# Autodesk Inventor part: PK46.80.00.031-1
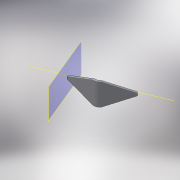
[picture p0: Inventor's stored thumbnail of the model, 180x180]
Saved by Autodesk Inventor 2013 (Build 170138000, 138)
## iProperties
Created: 2005-12
Part Number: PK46.80.00.031-1
Material: Steel, Mild
Document SubType Name: Листовой материал
Designer: SAlex
Manufacturer: Standard
Standards Organization: Custom
Density: 7.86 g/cm^3
Flat Pattern Width: 20.0383 cm
Flat Pattern Length: 20.0383 cm
Flat Pattern Area: 401.534 cm^2
Sheet Metal Rule: Default
Mass: 1079.17 g
Surface Area: 391.416 cm^2
Volume: 137.3 cm^3
Author: SAlex
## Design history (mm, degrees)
node "ФлнОтгиб1"
node "РабПлоскость1"
node "РабТочка1"
node "РабТочка2"
node "РабОсь1"
node "РабПлоскость2"
node "РабПлоскость3"
sketch "Эскиз4"
  geometry: L1 (141.716, 0)-(141.716, 150) reference; L2 (0, 150)-(141.716, 150) reference; L3 (0, 150)-(0, 0) reference; L4 (0, 0)-(141.716, 0) reference; L5 (141.716, 20.768)-(0, 75) reference; L6 (0, 75)-(141.716, 129.232) reference; 4 further points; 2 other entities
  constraints: 2 other
extrude "Выдавливание1" cut sketch "Эскиз4" stored distance "d11" = 10; taper "d12" = 0 deg
sketch "Эскиз5"
  geometry: L1 (141.716, 0)-(141.716, 150) reference; L2 (141.716, 150)-(0, 150) reference; L3 (0, 0)-(0, 150) reference; L4 (141.716, 0)-(0, 0) reference; L5 (0, 75)-(141.716, 129.232) reference; L6 (141.716, 20.768)-(0, 75) reference
extrude "Выдавливание2" cut sketch "Эскиз5" stored distance "d13" = 10; taper "d14" = 0 deg
node "РабПлоскость5"
sketch "Эскиз6"
  geometry: L1 (-127.655, 0)-(383.938, 0) reference; L2 (-37, -52.5)-(310.853, -52.5); L3 (310.853, -52.5)-(310.853, 52.5); L4 (310.853, 52.5)-(-37, 52.5); L5 (-37, 52.5)-(-37, -52.5)
  constraints: 8 end point, 2 parallel, 1 horizontal, 1 perpendicular
  dimensions: "d16" = 105 distance between parallel lines of L2 L4; "d17" = 52.5 distance between parallel lines of L1 L2 (= 0.5 x d16)
extrude "Выдавливание3" sketch "Эскиз6" stored distance "d18" = 10; taper "d19" = 0 deg
node "РабОсь2"
sketch "Эскиз7"
  geometry: L1 (0, 0)-(-137.189, -52.5) reference; L2 (-137.189, -52.5)-(0, -105) reference; L3 (4.527, -105)-(4.527, 0) reference; L4 (-122.189, -46.76)-(-122.189, -58.24)
  constraints: 2 end point, 2 point on line, 1 parallel
  dimensions: "d20" = 15 distance from line of L1.end L4
extrude "Выдавливание4" cut sketch "Эскиз7" stored distance "d21" = 10; taper "d22" = 0 deg
node "РабПлоскость6"
mirror "ЗеркОтобр1"
node "РабПлоскость7"
node "РабПлоскость8"
body "Solid1"
sketch "Эскиз2"
  geometry: L1 (146.236, -76.696)-(277.164, 0) reference; L2 (277.164, 0)-(280.225, -10.453) reference; L3 (280.225, -10.453)-(149.297, -87.149) reference; L4 (127.867, -87.149)-(-3.061, -10.453) reference; L5 (-3.061, -10.453)-(0, 0) reference; L6 (0, 0)-(130.928, -76.696) reference; 2 further points; 2 other entities
  constraints: 12 end point, 24 other
sketch "Эскиз3"
  geometry: L1 (130.928, 76.696)-(0, 0) reference; L2 (0, 0)-(-3.061, 10.453) reference; L3 (-3.061, 10.453)-(127.867, 87.149) reference; L4 (149.297, 87.149)-(280.225, 10.453) reference; L5 (280.225, 10.453)-(277.164, 0) reference; L6 (277.164, 0)-(146.236, 76.696) reference; 2 further points; 2 other entities
  constraints: 12 end point, 24 other
sketch "Эскиз1"
  geometry: L1 (-0.042, 0)-(149.958, 0); L2 (149.958, 0)-(256.024, 106.066)
  constraints: 4 end point, 1 equal length, 1 horizontal, 1 other
  dimensions: "d0" = 135 deg angle of L2 L1; "d1" = 150 distance of L1.start L1.end
feature "Плакирование1" dims "d2" = 150, "d3" = 8 (= BendReliefWidth), "d5" = 16 (= MinimumRemnant), "d7" = 20 (= BendRadius), "d8" = 8, "Thickness" = 8
feature "Изгиб1" dims "d3" = 8 (= BendReliefWidth), "d4" = 4 (= BendReliefDepth), "d5" = 16 (= MinimumRemnant), "d6" = 20 (= BendRadius), "d7" = 20 (= BendRadius), "d8" = 8, "SeamGap" = 0.01, "Thickness" = 8
node "Развертка"
feature "FlatPatternExtrusion2" dims "d0" = 8 (derived)
other parameters: "BendRadius" = 20, "BendReliefWidth" = 8 (= Thickness), "BendReliefDepth" = 4 (= 0.5 x Thickness), "CornerReliefSize" = 32 (= 4 x Thickness), "MinimumRemnant" = 16 (= 2 x Thickness), "d9" = 45 deg, "d10" = 90 deg, "d15" = 90 deg, "d23" = 90 deg, "d24" = 90 deg, "d25" = 90 deg, "JacobiRadiusSize" = 8 (= Thickness), "GapSize" = 8 (= Thickness)
